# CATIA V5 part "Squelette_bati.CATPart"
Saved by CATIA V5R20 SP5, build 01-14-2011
Part number: Squelette_bâti
Publications: "Plan xy", "Plan yz", "Plan zx", "Décallage_bas", "Hauteur_pivot_bâti", "Longueur_int_glissière_2", "Longueur_ext_glissiere_2", "Largeur_int_glissiere_2", "Largeur_ext_glissiere_2", "epaisseur_1_glissiere_2", "epaisseur_2_glissiere_2", "Longueur_socle_glissiere_2", "hauteur_pivot_2", "Décallage_pivot", "Point.1", "Point.2", "Point.3", "Point.4", "Point.5", "Point.6", "Point.7", "Point.8", "Droite.1", "Droite.2", "Droite.3", "Droite.4", "Droite.5", "Droite.6", "Droite.7", "Droite.8", "Point.9", "Droite.9", "Plan.1", "Point.10", "Droite.10"
Bounding box of the stored display mesh (mm): x 0 to 109.5, y -90 to 64, z 0 to 20
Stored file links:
  C:\Users\MARLENE\Documents\IFMA\S3\IAO\Copie de CAO\Squelette_bati.CATPart
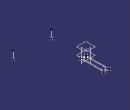
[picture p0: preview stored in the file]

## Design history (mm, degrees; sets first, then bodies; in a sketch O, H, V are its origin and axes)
Parameters
  `Décallage_bas` = 20 mm
  `Hauteur_pivot_bâti` = 18 mm
  `Longueur_int_glissière_2` = 58 mm
  Longueur_ext_glissiere_2 = 64 mm
  Largeur_int_glissiere_2 = 10 mm
  Largeur_ext_glissiere_2 = 15 mm
  epaisseur_1_glissiere_2 = 2.5 mm
  epaisseur_2_glissiere_2 = 3 mm
  Longueur_socle_glissiere_2 = 106 mm
  hauteur_pivot_2 = 16 mm
  `Décallage_pivot` = 102 mm
Set1
  Point1: (0, 0, 0)
  Point2: (15 {= Largeur_ext_glissiere_2}, 0, 0)
  Point3: (15 {= Largeur_ext_glissiere_2}, 64 {= Longueur_ext_glissiere_2}, 0)
  Point4: (0, 64 {= Longueur_ext_glissiere_2}, 0)
  Point5: (2.5 {= epaisseur_1_glissiere_2}, 3 {= epaisseur_2_glissiere_2}, 0)
  Point6: (2.5 {= epaisseur_1_glissiere_2}, 61 {= epaisseur_2_glissiere_2 +`Longueur_int_glissière_2`}, 0)
  Point7: (12.5 {= epaisseur_1_glissiere_2 +Largeur_int_glissiere_2}, 61 {= epaisseur_2_glissiere_2 +`Longueur_int_glissière_2`}, 0)
  Point8: (12.5 {= epaisseur_1_glissiere_2 +Largeur_int_glissiere_2}, 3 {= epaisseur_2_glissiere_2}, 0)
  Line1: type PtPt, FirstPoint Point3, SecondPoint Point2
  Line2: type PtPt, FirstPoint Point3, SecondPoint Point4
  Line3: type PtPt, FirstPoint Point4, SecondPoint Point1
  Line4: type PtPt, FirstPoint Point1, SecondPoint Point2
  Line5: type PtPt, FirstPoint Point5, SecondPoint Point6
  Line6: type PtPt, FirstPoint Point6, SecondPoint Point7
  Line7: type PtPt, FirstPoint Point7, SecondPoint Point8
  Line8: type PtPt, FirstPoint Point8, SecondPoint Point5
  Point9: (7.5 {= Largeur_ext_glissiere_2 /2}, -88 {= -(Longueur_socle_glissiere_2 -`Hauteur_pivot_bâti` )}, 0)
  Line9: type PtDir, RefPoint Point9, Direction xy-plane, Start 0, End 20
  Plane1: type Offset, RefPlane xy-plane, Offset 20
  Point10: (109.5 {= `Décallage_pivot` +Largeur_ext_glissiere_2 /2}, -90 {= -(Longueur_socle_glissiere_2 -hauteur_pivot_2 )}, 0)
  Line10: type PtDir, RefPoint Point10, Direction xy-plane, Start 0, End 20
Body1 (main body)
